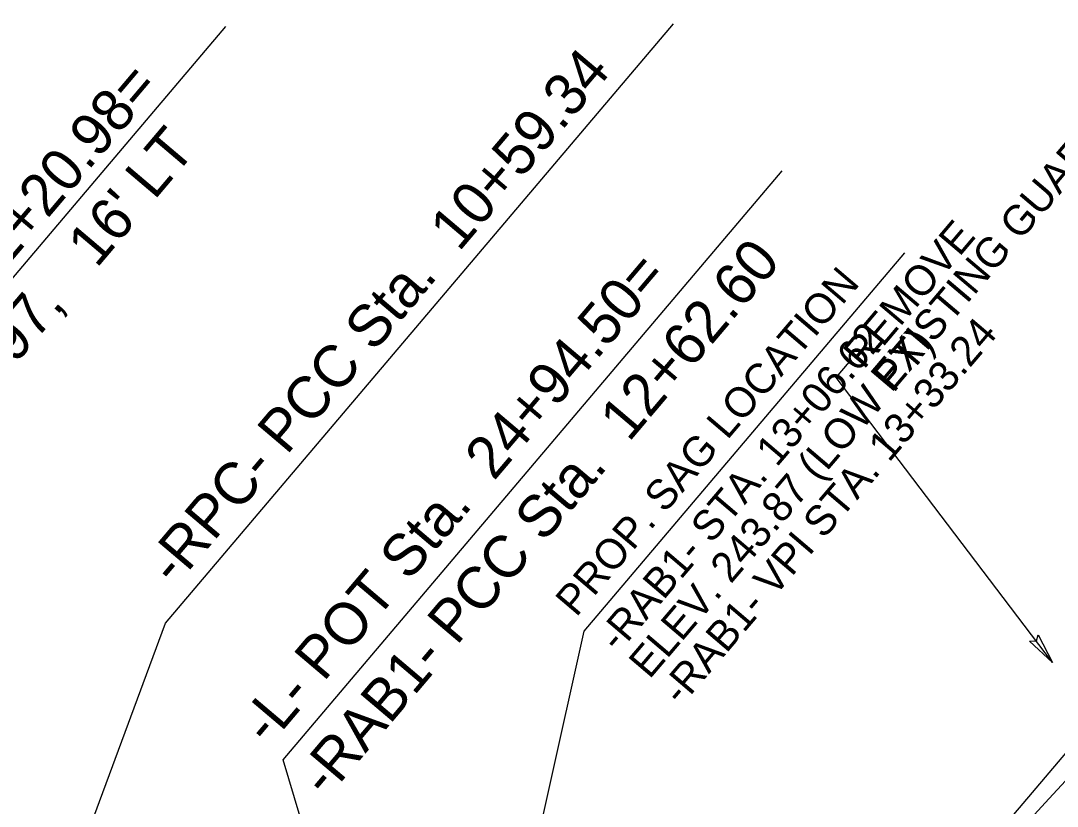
# Model space of a CAD drawing. Extents: x 1761082 to 1764358, y 421907 to 425434.
# Drawn here: x 1762165.7 to 1762337.6, y 423215.6 to 423346 of the extents above; entities that cross this region are included whole.
import ezdxf

# ---------------------------------------------------------------- set-up
doc = ezdxf.new("R2010")
doc.units = 0
for name, color, linetype in [('MARK UTURN ARROW CELL', 7, 'Continuous'), ('Prop Drainage Ditch Boundaries', 7, 'Continuous'), ('Prop Mkg Solid White Multiple Diagonals V8i', 7, 'Continuous'), ('Prop Mkg Solid Yel Skip LT', 7, 'Continuous'), ('Prop Mkg Solid Yel Skip RT', 7, 'Continuous'), ('Prop Mkg Solid Yellow Lane Line', 7, 'Continuous'), ('Scratch_Level_1', 7, 'Continuous')]:
    doc.layers.add(name, color=color, linetype=linetype)

msp = doc.modelspace()

# ---------------------------------------------------------------- linework, layer by layer
at = {"layer": 'MARK UTURN ARROW CELL'}
for points in [[(1762080.08, 423131.09), (1762106.58, 423235.12), (1762199.69, 423345.03)], [(1762125.93, 423073.81), (1762189.69, 423246.02), (1762273.94, 423345.46)], [(1762260.13, 423052.53), (1762209.2, 423223.34), (1762292, 423321.08)]]:
    msp.add_lwpolyline(points, dxfattribs=at)
at = {"layer": 'Prop Drainage Ditch Boundaries'}
msp.add_lwpolyline([(1762269.56, 423144.32), (1762275.35, 423150.62), (1762282.12, 423157.99), (1762288.89, 423165.36), (1762295.66, 423172.73), (1762302.44, 423180.1), (1762309.21, 423187.47), (1762315.98, 423194.84), (1762322.75, 423202.2), (1762329.52, 423209.57), (1762336.3, 423216.94), (1762343.07, 423224.31)], dxfattribs=at)
at = {"layer": 'Prop Mkg Solid White Multiple Diagonals V8i'}
msp.add_line((1762270.77, 423143.91), (1762579.6, 423508.45), dxfattribs=at)
at = {"layer": 'Prop Mkg Solid Yel Skip RT'}
msp.add_lwpolyline([(1762336.86, 423239.5), (1762300.95, 423286.82), (1762303.16, 423289.42)], dxfattribs=at)
at = {"layer": 'Prop Mkg Solid Yellow Lane Line'}
msp.add_lwpolyline([(1762334.48, 423244.1), (1762336.86, 423239.5), (1762333.04, 423243.04), (1762334.16, 423243.07)], close=True, dxfattribs=at)
at = {"layer": 'Scratch_Level_1'}
msp.add_lwpolyline([(1762218.3, 423060.96), (1762259.15, 423244.72), (1762312.32, 423307.47)], dxfattribs=at)

# ---------------------------------------------------------------- texts
at = {"layer": 'MARK UTURN ARROW CELL'}
for s, p in [('-RPC- PCC Sta.  12+20.61', (1762098, 423328.93)), ('-RPC- PCC Sta.  10+59.34', (1762191.3, 423251.97)), ('-SPURC- POT Sta.  12+20.98=', (1762104.71, 423235.86)), ("-RPC- Sta.  11+16.97,   16' LT", (1762113.53, 423228.39)), ('-RAB1- PCC Sta.  12+62.60', (1762216.46, 423216.8)), ('-L- POT Sta.  24+94.50=', (1762206.85, 423225.46))]:
    msp.add_text(s, height=7, rotation=49.7301, dxfattribs=at).set_placement(p)
at = {"layer": 'Prop Mkg Solid Yel Skip LT'}
for s, p in [('EXISTING GUARDRAIL', (1762310.12, 423284.13)), ('REMOVE', (1762305.54, 423288.01))]:
    msp.add_text(s, height=5, rotation=49.7301, dxfattribs=at).set_placement(p)
at = {"layer": 'Scratch_Level_1'}
for s, p in [('PROP. SAG LOCATION', (1762257.82, 423246.9)), ('-RAB1- STA. 13+06.62', (1762264.82, 423240.97)), ('-RAB1- VPI STA. 13+33.24', (1762275.25, 423232.14)), ('ELEV. 243.87 (LOW PT)', (1762269.98, 423236.6))]:
    msp.add_text(s, height=5, rotation=49.5644, dxfattribs=at).set_placement(p)

doc.saveas('drawing.dxf')
